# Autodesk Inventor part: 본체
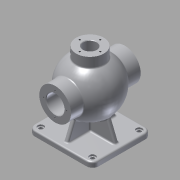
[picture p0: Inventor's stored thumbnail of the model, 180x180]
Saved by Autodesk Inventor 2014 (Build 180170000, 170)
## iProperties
Created: 2015-10
Part Number: 본체
Material: 알루미늄 6061
Document SubType Name: Modeling
Designer: youjin16
Density: 2.71 g/cm^3
Appearance: 알루미늄 - 평지
Mass: 1509.66 g
Surface Area: 1153.54 cm^2
Volume: 557.069 cm^3
Author: youjin16
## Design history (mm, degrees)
sketch "스케치1"
  geometry: L1 (-50.5, -57.5)-(50.5, -57.5); L2 (62.5, -45.5)-(62.5, 45.5); L3 (50.5, 57.5)-(-50.5, 57.5); L4 (-62.5, 45.5)-(-62.5, -45.5); L5 (-62.5, -57.5)-(62.5, 57.5); L6 (62.5, -57.5)-(-62.5, 57.5); C1 r 4 at (-50.5, 45.5); C2 r 4 at (50.5, 45.5); C3 r 4 at (-50.5, -45.5); C4 r 4 at (50.5, -45.5); A1 r 12 centre (-50.5, 45.5) between (-50.5, 57.5) and (-62.5, 45.5); A2 r 12 centre (-50.5, -45.5) between (-62.5, -45.5) and (-50.5, -57.5); A3 r 12 centre (50.5, 45.5) between (62.5, 45.5) and (50.5, 57.5); A4 r 12 centre (50.5, -45.5) between (50.5, -57.5) and (62.5, -45.5); 1 further point
  constraints: 12 end point, 8 centre point, 8 point on circle, 8 point on line, 8 tangent, 4 coincident, 3 equal radius, 2 midpoint, 2 parallel, 1 horizontal, 1 perpendicular
  dimensions: "d0" = 125 distance of L6.end L5.end; "d1" = 115 distance of L5.end L6.start; "d2" = 12 radius of A1; "d3" = 8 diameter of C1; "d4" = 8 diameter of C2; "d5" = 8 diameter of C3; "d6" = 8 diameter of C4
extrude "돌출1" new body sketch "스케치1" distance "d7" = 10; taper "d8" = 0 deg
sketch "스케치2"
  geometry: C1 r 4 at (50.5, -45.5) reference; C2 r 4 at (-50.5, -45.5) reference; C3 r 4 at (50.5, 45.5) reference; C4 r 4 at (-50.5, 45.5) reference; C5 r 6 at (-50.5, 45.5); C6 r 6 at (-50.5, -45.5); C7 r 6 at (50.5, -45.5); C8 r 6 at (50.5, 45.5); A1 r 12 centre (-50.5, -45.5) between (-62.5, -45.5) and (-50.5, -57.5) reference; A2 r 12 centre (50.5, -45.5) between (50.5, -57.5) and (62.5, -45.5) reference; A3 r 12 centre (50.5, 45.5) between (62.5, 45.5) and (50.5, 57.5) reference; A4 r 12 centre (-50.5, 45.5) between (-50.5, 57.5) and (-62.5, 45.5) reference; 1 further point
  constraints: 4 centre point, 4 coincident
  dimensions: "d9" = 12 diameter of C5; "d10" = 12 diameter of C6; "d11" = 12 diameter of C7; "d12" = 12 diameter of C8
extrude "돌출2" cut sketch "스케치2" distance "d13" = 3; taper "d14" = 0 deg
sketch "스케치3"
  geometry: L1 (0, 138)-(0, 32); A1 r 53 centre (0, 85) between (0, 138) and (0, 32); A2 r 53 centre (0, 85) between (0, 32) and (0, 138); 2 further points
  constraints: 4 point on circle, 2 centre point, 2 end point, 2 vertical alignment, 1 midpoint, 1 vertical
  dimensions: "d15" = 106 diameter of A1; "d16" = 85 distance of point (0, 0) A1.centre
revolve "회전1" sketch "스케치3" stored, may be unused: angle "d17" = 90 deg
node "작업 평면1"
sketch "스케치4"
  geometry: C1 r 31 at (0, 85); 1 further point
  constraints: 1 centre point, 1 vertical alignment
  dimensions: "d19" = 62 diameter of C1; "d20" = 85 distance of point (0, 0) C1.centre
extrude "돌출3" join sketch "스케치4" distance "d21" = 136; taper "d22" = 0 deg
node "작업 평면2"
sketch "스케치5"
  geometry: C1 r 27 at (0, 0); 1 further point
  constraints: 1 centre point, 1 coincident
  dimensions: "d24" = 54 diameter of C1
extrude "돌출4" join sketch "스케치5" stored distance "d25" = 136; taper "d26" = 0 deg
sketch "스케치8"
  geometry: L1 (-27, 130.607)-(27, 130.607) reference; L2 (0, 128)-(0, 42); C1 r 31 at (0, 85) reference; C2 r 31 at (0, 85) reference; A1 r 43 centre (0, 85) between (0, 128) and (0, 42); A2 r 43 centre (0, 85) between (0, 42) and (0, 128); 2 further points
  constraints: 4 point on circle, 2 centre point, 2 end point, 2 vertical alignment, 1 coincident, 1 midpoint
  dimensions: "d39" = 86 diameter of A1
revolve "회전2" sketch "스케치8" stored, may be unused: angle "d40" = 90 deg
sketch "스케치9"
  geometry: C1 r 31 at (0, 0) reference; C2 r 17.5 at (0, 0); 1 further point
  constraints: 1 centre point, 1 coincident
  dimensions: "d41" = 35 diameter of C2
extrude "돌출7" cut sketch "스케치9" stored distance "d42" = 8; taper "d43" = 0 deg
sketch "스케치10"
  geometry: C1 r 31 at (0, 0) reference; C2 r 17.5 at (0, 0); 1 further point
  constraints: 1 centre point, 1 coincident
  dimensions: "d44" = 35 diameter of C2
extrude "돌출8" cut sketch "스케치10" distance "d45" = 16; taper "d46" = 0 deg
sketch "스케치11"
  geometry: C1 r 17.5 at (0, 0) reference; C2 r 18.5 at (0, 0); 1 further point
  constraints: 1 centre point, 1 coincident
  dimensions: "d47" = 37 diameter of C2
extrude "돌출9" cut sketch "스케치11" distance "d48" = 1.75; taper "d49" = 0 deg
sketch "스케치12"
  geometry: C1 r 18.5 at (0, 0) reference; C2 r 17.5 at (0, 0); 1 further point
  constraints: 1 centre point, 1 coincident
  dimensions: "d50" = 35 diameter of C2
extrude "돌출10" cut sketch "스케치12" stored distance "d51" = 1.75; taper "d52" = 0 deg
sketch "스케치13"
  geometry: C1 r 27 at (0, 0) reference; C2 r 13 at (0, 0)
  constraints: 1 centre point, 1 coincident
  dimensions: "d53" = 26 diameter of C2
extrude "돌출11" cut sketch "스케치13" stored distance "d54" = 1.75; taper "d55" = 0 deg
sketch "스케치14"
  geometry: C1 r 13 at (0, 0) reference; C2 r 27 at (0, 0) reference; A1 r 20 centre (0, 0) between (-20, 0) and (0, 20); 2 further points
  constraints: 4 point on circle, 2 horizontal alignment, 2 vertical alignment, 1 centre point, 1 coincident
  dimensions: "d56" = 40 diameter of A1
hole "구멍1" sketch "스케치14" at (-20, 0), (0, 20), (20, 0), (0, -20) diameter "d57" = 3.242; stored, may be unused: countersink angle "d61" = 90 deg, drill point angle "d63" = 0 deg; dims "d58" = 9, "d59" = 35, "d60" = 16, "d62" = 11
sketch "스케치15"
  geometry: C1 r 17.5 at (0, 0) reference; C2 r 31 at (0, 0) reference; A1 r 22.5 centre (0, 0) between (-22.5, 0) and (0, 22.5); 3 further points
  constraints: 4 point on circle, 2 horizontal alignment, 2 vertical alignment, 1 centre point, 1 coincident
  dimensions: "d64" = 45 diameter of A1
hole "구멍2" sketch "스케치15" at (-22.5, 0), (0, 22.5), (22.5, 0), (0, -22.5) diameter "d65" = 3.242; stored, may be unused: countersink angle "d69" = 90 deg, drill point angle "d71" = 0 deg; dims "d66" = 12, "d67" = 35, "d68" = 16, "d70" = 15
sketch "스케치16"
  geometry: C1 r 17.5 at (0, 0) reference; C2 r 31 at (0, 0) reference; A1 r 24 centre (0, 0) between (0, 24) and (24, 0); 3 further points
  constraints: 4 point on circle, 2 horizontal alignment, 2 vertical alignment, 1 centre point, 1 coincident
  dimensions: "d72" = 48 diameter of A1
hole "구멍3" sketch "스케치16" at (0, 24), (24, 0), (-24, 0), (0, -24) diameter "d73" = 3.242; stored, may be unused: countersink angle "d77" = 90 deg, drill point angle "d79" = 0 deg; dims "d74" = 16, "d75" = 35, "d76" = 16, "d78" = 19
node "작업 평면3"
sketch "스케치17"
  geometry: L1 (-27, 150)-(27, 150) reference; 3 further points
  constraints: 1 midpoint, 1 vertical alignment, 1 other
  dimensions: "d81" = 10 vertical distance of L1.end point (0, 140)
feature "엠보싱1" dims "d82" = 0.5, "d83" = 0
sketch "스케치24"
  geometry: L1 (-4, -4)-(4, -4); L2 (4, -4)-(4, 4); L3 (4, 4)-(-4, 4); L4 (-4, 4)-(-4, -4); L5 (-4, -4)-(4, 4); L6 (4, -4)-(-4, 4); 3 further points
  constraints: 12 end point, 3 midpoint, 2 parallel, 1 coincident, 1 horizontal, 1 perpendicular
  dimensions: "d84" = 8 distance of L3.end L2.end; "d85" = 8 distance of L2.end L1.end
extrude "돌출12" join sketch "스케치24" stored distance "d86" = 50; taper "d87" = 0 deg
sketch "스케치25"
  geometry: L1 (4, 32.303)-(4, 32.303) reference; L2 (-4, 32.303)-(-4, 32.303) reference; L3 (-27, 130.607)-(27, 130.607) reference; L4 (-50.5, 10)-(50.5, 10) reference; L5 (-50.5, 10)-(-62.5, 10) reference; L6 (62.5, 10)-(50.5, 10) reference; L7 (-37.379, 47.426)-(-52.5, 10); L8 (37.379, 47.426)-(52.5, 10); C1 r 31 at (0, 85) reference; C2 r 31 at (0, 85) reference; A1 r 52.849 centre (0, 85) between (-4, 32.303) and (4, 32.303) reference; A2 r 52.849 centre (0, 85) between (-4, 32.303) and (4, 32.303) reference; A3 r 53 centre (0, 85) between (-27, 130.607) and (27, 130.607) reference; 1 further point
  constraints: 4 end point, 2 point on circle, 2 point on line
  dimensions: "d88" = 112 deg angle of L5 L7; "d89" = 10 distance of L5.end L7.end; "d90" = 112 deg angle of L6 L8; "d91" = 10 distance of L6.start L8.end
  node "투영된 루프15"
feature "리브1" dims "d92" = 1, "d93" = 8, "d94" = 0, "d95" = 0, "d96" = 1, "d97" = 1
feature "리브2" dims "d98" = 1, "d99" = 8, "d100" = 0, "d101" = 0, "d102" = 1, "d103" = 1
sketch "스케치26"
  geometry: L1 (45.5, 10)-(-45.5, 10) reference; L2 (39.5, 10)-(51.5, 10) reference; L3 (-51.5, 10)-(-39.5, 10) reference; L4 (-45.5, 10)-(-57.5, 10) reference; L5 (57.5, 10)-(45.5, 10) reference; L6 (-47.5, 10)-(-33.719, 44.109); L7 (33.719, 44.109)-(47.5, 10); A1 r 53 centre (0, 85) between (42.988, 116) and (42.988, 54) reference; 1 further point
  constraints: 4 end point, 2 point on circle, 2 point on line
  dimensions: "d104" = 112 deg angle of L4 L6; "d105" = 112 deg angle of L5 L7; "d106" = 10 distance of L5.start L7.end; "d107" = 10 distance of L4.end L6.start
feature "리브3" dims "d108" = 1, "d109" = 8, "d110" = 0, "d111" = 0, "d112" = 1, "d113" = 1
feature "리브4" dims "d114" = 1, "d115" = 8, "d116" = 0, "d117" = 0, "d118" = 1, "d119" = 1
fillet "모깎기1" dims "d120" = 3
chamfer "모따기1" distance "d121" = 1; stored, may be unused: second distance "d122" = 2, angle "d123" = 45 deg
chamfer "모따기2" distance "d124" = 1; stored, may be unused: second distance "d125" = 2, angle "d126" = 45 deg
chamfer "모따기3" distance "d127" = 1; stored, may be unused: second distance "d128" = 2, angle "d129" = 45 deg
node "솔리드1"
node "투영된 루프10"
other parameters: "d18" = -68, "d80" = -27.5
